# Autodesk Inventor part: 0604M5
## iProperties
Shininess: 60.0
Length Units: 11269
Angle Units: 11279
Time Units: 11290
Mass Units: 11283
Length Display Precision: 3
Angle Display Precision: 2
Compacted: True
Company: Pneumax S.p.A.
Part Number: 0604M5
Description: ADATTATORE MASCHIO M5 Ø4
Document SubType Name: Modellazione
Catalog Web Link: www.pneumaxspa.com
Density: 0.0
Volumn: 0.0
Area: 0.0
PropertySet Name: Model Information
Control State: 0
Master: False
Checked Out: False
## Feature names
1. Rivoluzione1 [Revolution]
2. Extrusion3
3. Circular Pattern2
4. Smusso3 [Chamfer]
5. Chamfer5
